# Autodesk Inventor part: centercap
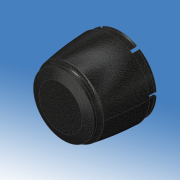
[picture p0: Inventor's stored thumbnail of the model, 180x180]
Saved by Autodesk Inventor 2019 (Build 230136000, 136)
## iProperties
Created: 2021-04
Part Number: centercap
Material: Generic
Document SubType Name: Modeling
Designer: Caden
Density: 1 g/cm^3
Appearance: Default
Author: Caden
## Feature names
1. Extrusion1
2. Loft1
3. Extrusion2
4. Fillet1
5. Loft2
6. Extrusion5
7. Circular Pattern1
8. Shell3
9. Extrusion6
10. Chamfer1
11. Sweep1
12. Circular Pattern2
## Parameters: d0 = 73.152 mm, d1 = 76.962 mm, d2 = 8.89 mm, d3 = 0, d4 = 81.28 mm, d5 = 44.45 mm, d6 = 71.882 mm, d7 = 78.232 mm, d8 = 0, d9 = 90 deg, d10 = 0, d11 = 90 deg, d12 = 0, d13 = 90 deg, d14 = 7.366 mm, d15 = 65.532 mm, d16 = 8.89 mm, d17 = 0, d18 = 5.08 mm, d19 = 3.556 mm, d20 = 46.482 mm, d21 = 0, d22 = 90 deg, d23 = 0, d24 = 90 deg, d31 = 7.8232 mm, d32 = 0, d34 = 360 deg, d38 = 4.572 mm, d39 = 12.7 mm, d40 = 0, d41 = 1.143 mm, d42 = 3.175 mm, d43 = 45 deg, d45 = 0, d46 = 0.762 mm, d47 = 0, d48 = 0, d50 = 360 deg
